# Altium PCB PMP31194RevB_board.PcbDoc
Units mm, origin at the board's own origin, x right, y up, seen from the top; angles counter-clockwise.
Board outline 68.58 x 39.37 mm, 2 copper layers (Top Layer, Bottom Layer), stack 1.575 mm thick; 43 components, 19 nets, 101 pads, 38 vias.
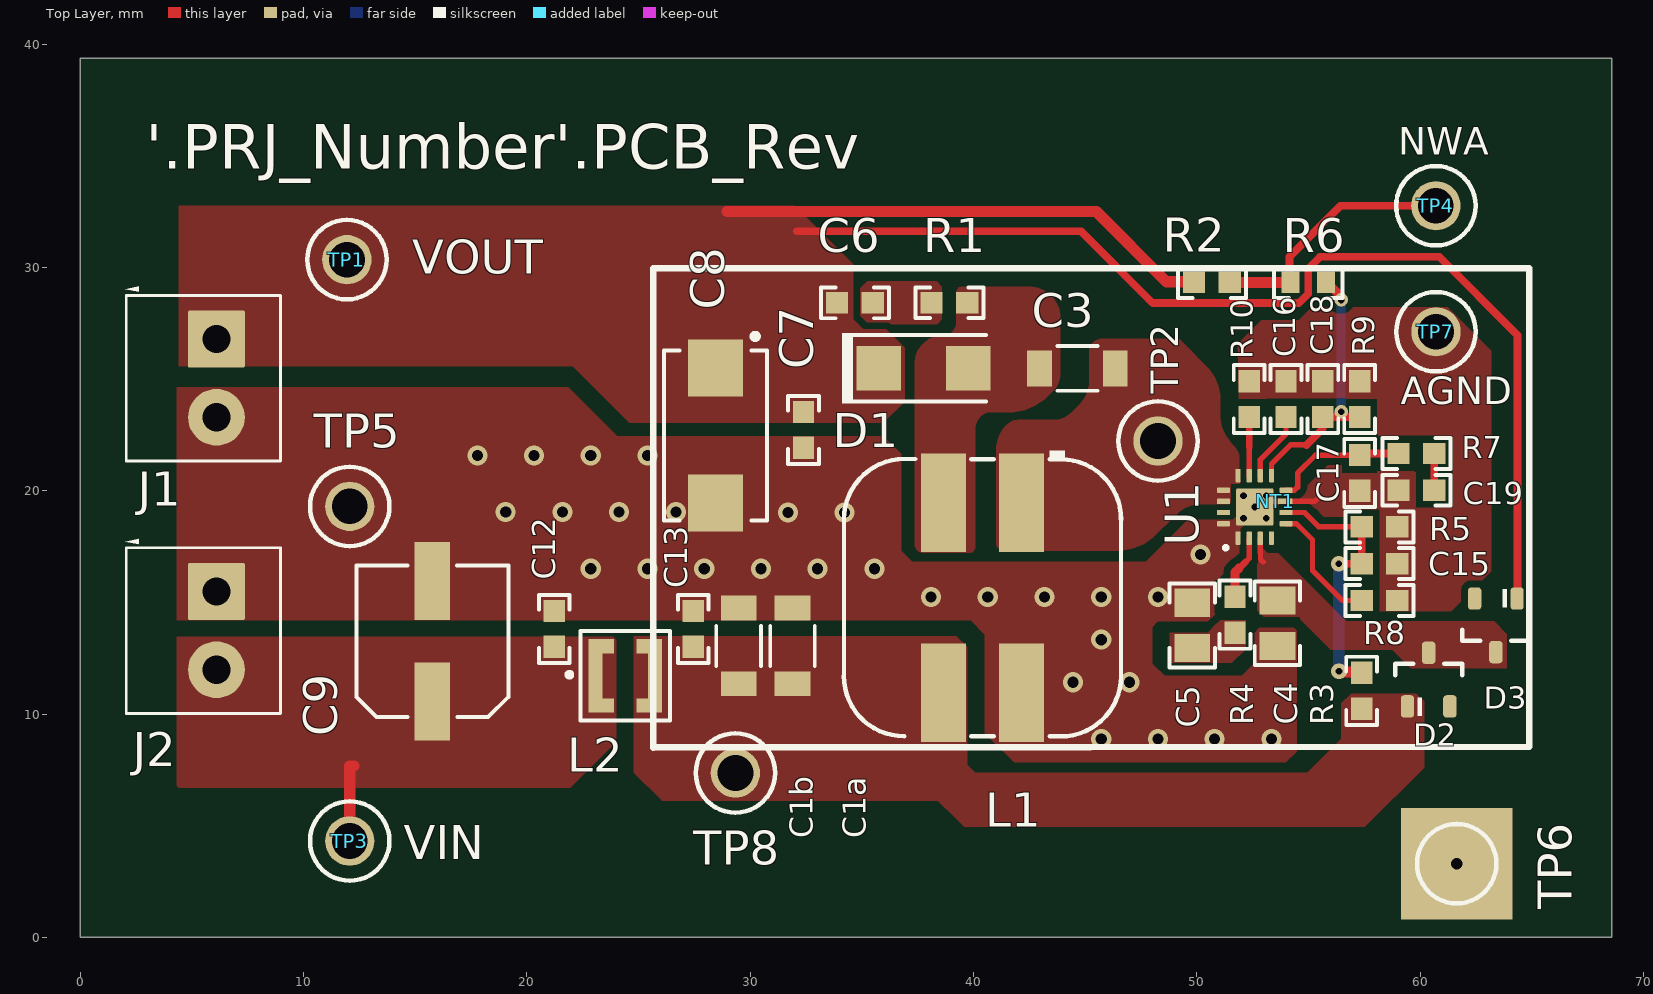
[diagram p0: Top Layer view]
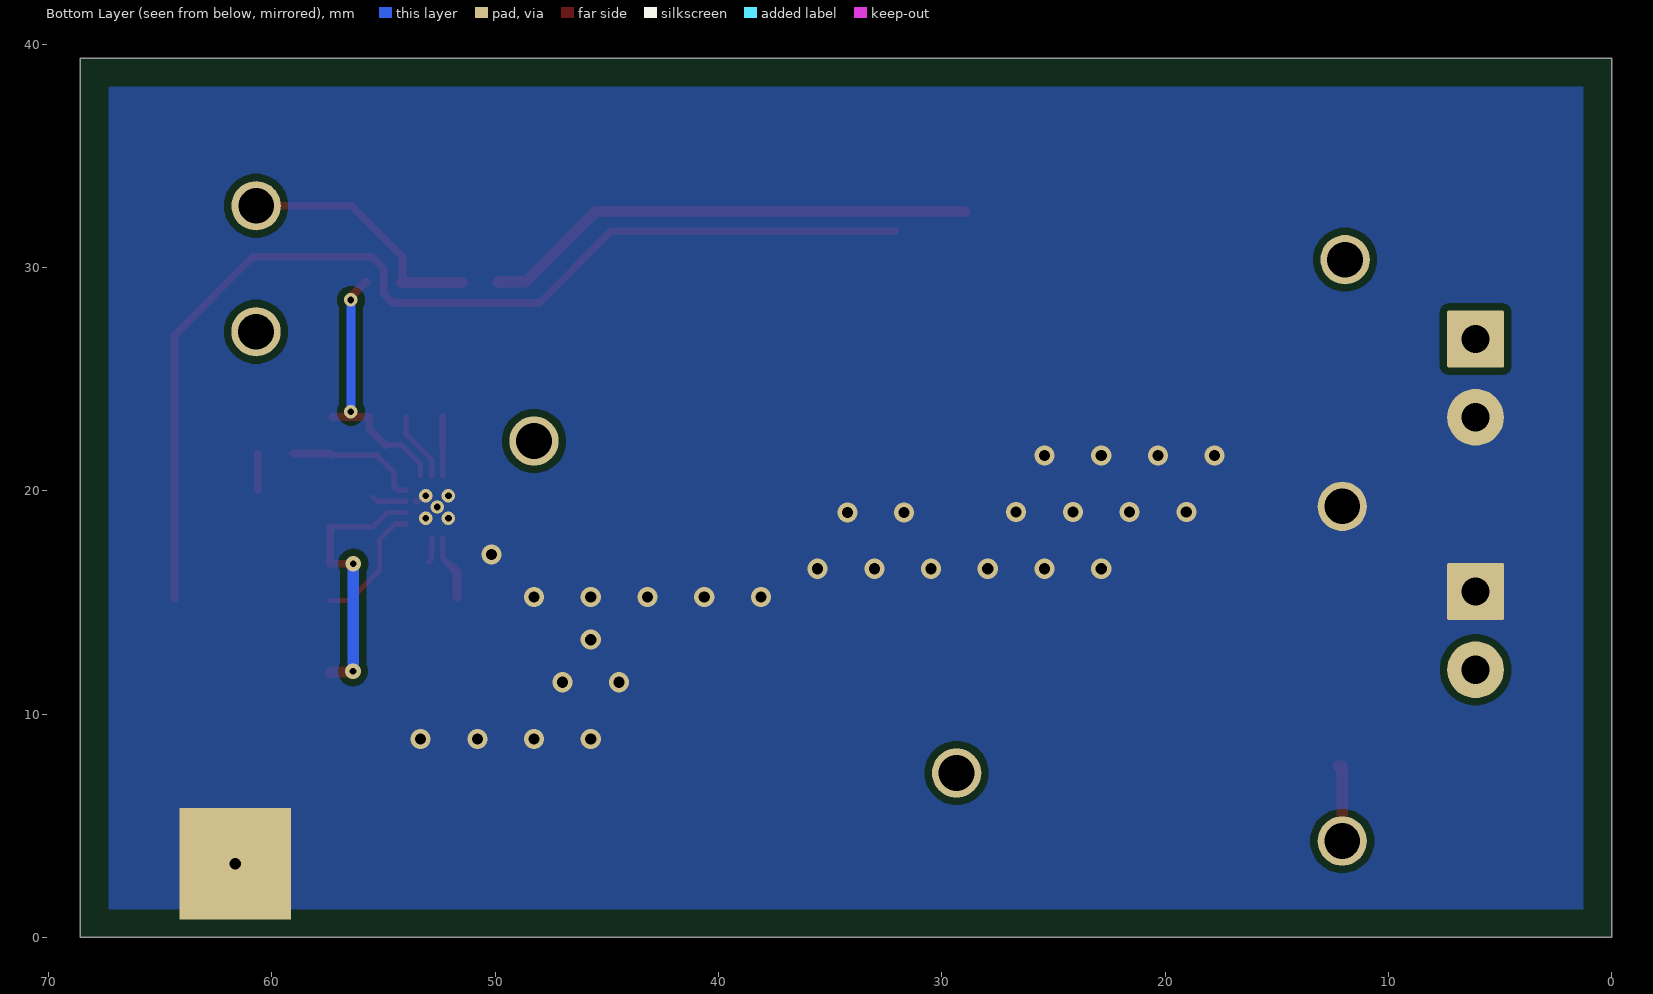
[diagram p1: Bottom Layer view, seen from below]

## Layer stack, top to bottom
Top Solder: solder mask 0.0102, Solder Resist, Dk 3.5
Top Layer: signal copper 0.0356
Dielectric1: core 1.5037, FR-4, Dk 4.8
Bottom Layer: signal copper 0.0356
Bottom Solder: solder mask 0.0102, Solder Resist, Dk 3.5

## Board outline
0,0 68.58,0 68.58,39.37 0,39.37

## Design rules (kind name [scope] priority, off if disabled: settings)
AcuteAngle [All] p1: minimum=4.50000000000000E+0001 checktracksonly=FALSE
AssemblyTestPointUsage [All] p1: valid=2
BoardOutlineClearance BoardOutlineClearance_MountingHoles [OnCopper and InComponentClass('Mounting Holes')] p1: gap=1 ignorepadtopadclearanceinfootprint=FALSE
BoardOutlineClearance BoardOutlineClearance_Poly [OnCopper and IsPoly] p2: gap=0.635 ignorepadtopadclearanceinfootprint=FALSE
BoardOutlineClearance [OnCopper and Not InComponentClass('Logo') and not InComponentClass('FiducialMark') and not InRegion(1000,500,4000,800) and not InPoly] p3: gap=1.905 ignorepadtopadclearanceinfootprint=FALSE
Clearance Clearance_Keepouts [((IsTrack Or IsArc) And Not InPoly) And IsFree and IsKeepOut vs ((IsTrack Or IsArc) And Not InPoly) And IsFree and IsKeepOut] p1: gap=0 ignorepadtopadclearanceinfootprint=FALSE
Clearance Clearance_Poly_U1 [InPolygon vs InComponent('U1')] p2: gap=0.2 ignorepadtopadclearanceinfootprint=TRUE
Clearance Clearance_Poly [InPolygon] p3: gap=0.32 ignorepadtopadclearanceinfootprint=TRUE
Clearance Clearance_FiducialMark [IsKeepOut and InComponentClass('FiducialMark') vs IsPad and InComponentClass('FiducialMark')] p4: gap=0 ignorepadtopadclearanceinfootprint=FALSE
Clearance [All] p5: gap=0.2 ignorepadtopadclearanceinfootprint=TRUE
ComponentClearance ComponentClearance_Net-Tie [HasFootprint('Net-Tie_10mil') vs HasFootprint('RTE0016K')] p1: gap=0 collisioncheckmode=3 verticalgap=0 showdistances=FALSE
ComponentClearance ComponentClearance_MountingHoles_FiducialMarks [InComponentClass('Mounting Holes') vs InComponentClass('FiducialMark')] p2: gap=1.27 collisioncheckmode=3 verticalgap=0.254 showdistances=FALSE
ComponentClearance ComponentClearance_Shunt [InComponentClass('Header') vs InComponentClass('Shunt')] p3: gap=0 collisioncheckmode=3 verticalgap=0 showdistances=FALSE
ComponentClearance ComponentClearance_Logo [InComponentClass('Logo')] p4: gap=1.27 collisioncheckmode=3 verticalgap=0.254 showdistances=FALSE
ComponentClearance ComponentClearance_ScrewToNut [(HasFootprint('NY PMS 440 0025 PH')) vs (HasFootprint('Keystone_1902C'))] p5: gap=0.127 collisioncheckmode=3 verticalgap=0.254 showdistances=FALSE
ComponentClearance ComponentClearance_MountingHoles [InComponentClass('Mounting Holes')] p6: gap=6.35 collisioncheckmode=3 verticalgap=2540 showdistances=FALSE
ComponentClearance ComponentClearance_SmallPassives [HasFootprint('0201*') or HasFootprint('0402*') or HasFootprint('0508') or HasFootprint('0603*') or HasFootprint('0612') or HasFootprint('0805*') or HasFootprint('0815*') or HasFootprint('0830*') or HasFootprint('1206*') or HasFootprint('1210*') or HasFootprint('1808*') or HasFootprint('1812*') or HasFootprint('1825*') or HasFootprint('2010*') or HasFootprint('2220*') or HasFootprint('2225*') or HasFootprint('2512*') or HasFootprint('2728*') or HasFootprint('3518*') vs HasFootprint('0201*') or HasFootprint('0402*') or HasFootprint('0508') or HasFootprint('0603*') or HasFootprint('0612') or HasFootprint('0805*') or HasFootprint('0815*') or HasFootprint('0830*') or HasFootprint('1206*') or HasFootprint('1210*') or HasFootprint('1808*') or HasFootprint('1812*') or HasFootprint('1825*') or HasFootprint('2010*') or HasFootprint('2220*') or HasFootprint('2225*') or HasFootprint('2512*') or HasFootprint('2728*') or HasFootprint('3518*')] p7: gap=0.38 collisioncheckmode=3 verticalgap=0.254 showdistances=FALSE
ComponentClearance ComponentClearance_THtoSMT [IsThruComponent vs IsSMTComponent] p8: gap=1.016 collisioncheckmode=3 verticalgap=0.762 showdistances=FALSE
ComponentClearance ComponentClearance_THtoTH [IsThruComponent vs IsThruComponent] p9: gap=0.762 collisioncheckmode=3 verticalgap=0.762 showdistances=FALSE
ComponentClearance [All] p10: gap=0.762 collisioncheckmode=3 verticalgap=0.254 showdistances=FALSE
DiffPairsRouting [All] p1: maxlimit=2.54 minlimit=0.254 mostfreqgap=0.254 toplayer_minwidth=0.381 toplayer_maxwidth=0.381 toplayer_prefwidth=0.381 bottomlayer_minwidth=0.381 bottomlayer_maxwidth=0.381 bottomlayer_prefwidth=0.381 maxuncoupledlength=25.4
FabricationTestPointUsage TestPointUsage [All] p1: valid=2 allowmultiple=FALSE
FabricationTestpoint Testpoint [All] p1: side=3 testpointundercomponent=TRUE minsize=1.016 maxsize=2.54 preferedsize=1.524 minholesize=0 maxholesize=1.016 preferedholesize=0.813 testpointgrid=0.025 allowsidetop=TRUE allowsidebottom=TRUE usegrid=TRUE gridtolerance=0
FanoutControl Fanout_LCC [IsLCC] p1: bgadir=Out bgaviamode=Centered fanoutstyle=Auto fanoutdirection=Alternating viagrid=0.025 // Fanout_LCC (Default Rule)
FanoutControl Fanout_BGA [IsBGA] p2: bgadir=Out bgaviamode=Centered fanoutstyle=Auto fanoutdirection=Alternating viagrid=0.025 // Fanout_BGA (Default Rule)
FanoutControl Fanout_Default [All] p4: bgadir=Out bgaviamode=Centered fanoutstyle=Auto fanoutdirection=Alternating viagrid=0.025 // Fanout_Default (Default Rule)
FanoutControl Fanout_Small [(CompPinCount < 5)] p5: bgadir=Out bgaviamode=Centered fanoutstyle=Auto fanoutdirection=OutThenIn viagrid=0.025 // Fanout_Small (Default Rule)
HoleSize [All] p1: absolutevalues=TRUE maxlimit=6.375 minlimit=0.3 maxpercent=80.000 minpercent=20.000
MinimumAnnularRing MinimumAnnularRing_ThermalPadVias [IsVia and InAnyComponent] p1: minimumring=0.15
MinimumAnnularRing [All] p2: minimumring=0.2
MinimumSolderMaskSliver MinimumSolderMaskSliver_Logo [InComponentClass('Logo') vs InComponentClass('Logo')] p1: minsoldermaskwidth=0.018
MinimumSolderMaskSliver [All] p2: minsoldermaskwidth=0.1
PlaneConnect [All] p1: planeconnectstyle=Relief reliefexpansion=0.254 reliefentries=4 reliefconductorwidth=0.254 reliefairgap=0.254
PolygonConnect [All] p1: connectstyle=Direct reliefconductorwidth=0.254 reliefentries=4 polygonreliefangle="90 Angle" airgapwidth=0.254
RoutingVias ThermalPadVias [IsVia and InAnyComponent] p1: holewidth=0.2 width=0.5 viastyle="Through Hole" minholewidth=0.2 minwidth=0.5 maxholewidth=0.33 maxwidth=0.6
RoutingVias [All] p2: holewidth=0.5 width=0.9 viastyle="Through Hole" minholewidth=0.3 minwidth=0.6 maxholewidth=1.016 maxwidth=1.651
SilkToBoardRegionClearance [Not ((IsComment or IsDesignator) And (Hide <> 'False')) and not InRegion(1000,500,4000,800)] p1:
SilkToSilkClearance SilkToSilkClearance_Pb-FreeLogo [(HasFootprint('Pb-Free_Overlay_Medium') OR HasFootprint('Pb-Free_Overlay_Small')) vs (HasFootprint('Pb-Free_Overlay_Medium') OR HasFootprint('Pb-Free_Overlay_Small'))] p1: silktosilkclearance=0
SilkToSilkClearance [All] p2: silktosilkclearance=0.1
SilkToSolderMaskClearance SilkToComponentPadClearance [(IsPad or IsFill or IsRegion) and InAnycomponent] p1: minsilkscreentomaskgap=0.127 clearancetoexposedcopper=TRUE
SilkToSolderMaskClearance "Silk to Solder Mask Opening" [All] p2: minsilkscreentomaskgap=0.1 clearancetoexposedcopper=FALSE
SolderMaskExpansion [All] p1: expansion=0.05 istentingtop=FALSE
UnRoutedNet [All] p1: checkbadconnections=TRUE
Width [All] p1: maxlimit=2.54 minlimit=0.152 preferedwidth=0.254 checkconnectedcopper=TRUE
14 further rules are at their usual default settings.

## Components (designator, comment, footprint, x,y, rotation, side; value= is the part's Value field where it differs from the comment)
C1a "GRM31CR71H475KA12L" 1206_180 31.894,13.054 r90 top value=4.7uF
C1b "GRM31CR71H475KA12L" 1206_180 29.481,13.054 r90 top value=4.7uF
C3 "GRM31CR71H475KA12L" 1206_180 44.654,25.483 r0 top value=4.7uF
C4 "GRM21BR71H105KA12L" 0805_HV 53.611,14.07 r90 top value=1uF
C5 "GRM21BR71A105KA01L" 0805_HV 49.801,13.976 r90 top value=1uF
C6 "GCM1885C2A101JA16D" 0603#1 34.688,28.421 r180 top value=100pF
C7 "GRM188R71E104KA01D" 0603#1 32.385,22.733 r270 top value=0.1uF
C8 "T598D227M010ATE025" 7343-31 28.448,22.479 r270 top value=220uF
C9 "EEHZC1H330XP" SM_RADIAL_6.3BMM 15.765,13.266 r90 top value=33uF
C12 "GCM188R71H104KA57D" 0603#1 21.226,13.816 r90 top value=0.1uF
C13 "GCM188R71H104KA57D" 0603#1 27.449,13.816 r90 top value=0.1uF
C15 "GRM1885C1H100JA01D" 0603#1 58.183,16.737 r0 top value=10pF
C16 "GRM188R71E104KA01D" 0603#1 53.992,24.103 r90 top value=0.1uF
C17 "GRM188R71E222KA01D" 0603#1 57.294,20.801 r270 top value=2200pF
C18 "GRM1885C1H470JA01D" 0603#1 55.643,24.103 r90 top value=47pF
C19 "GRM188R71C154KA01D" 0603#1 59.834,20.027 r180 top value=0.15uF
D1 "B360AM-13-F" SMA 37.762,25.483 r0 top value=60V
D2 "ZHCS506TA" SOT-23 60.384,11.547 r90 top value=60V
D3 "ZHCS506TA" SOT-23 63.39,13.976 r270 top value=60V
J1 "ED555/2DS" TERM_BLK_ED555-2DS 6.096,26.797 r270 top
J2 "ED555/2DS" TERM_BLK_ED555-2DS 6.096,15.494 r270 top
L1 "MSC1278-103ML" MSD1278 40.403,15.213 r270 top value=10uH
L2 "LPS3015-102MLB" LPS3015 24.401,11.716 r0 top value=1uH
NT1 "Net-Tie" Net-Tie_10mil 53.517,19.527 r180 top net-tie
R1 "CRCW060310R0JNEAHP" 0603#1 38.917,28.421 r0 top value=10
R2 "CRCW060349R9FKEA" 0603#1 50.673,29.337 r180 top value=49.9
R3 "CRCW0603261KFKEA" 0603#1 57.383,11.047 r270 top value=261k
R4 "CRCW06034R99FKEA" 0603#1 51.706,14.451 r270 top value=4.99
R5 "CRCW060386K6FKEA" 0603#1 58.183,18.388 r180 top value=86.6k
R6 "CRCW060330K1FKEA" 0603#2 54.991,29.337 r180 top value=30.1k
R7 "CPF0603B4K99E" 0603#1 59.834,21.676 r180 top value=4.99k
R8 "CRCW060349K9FKEA" 0603#1 58.183,15.086 r180 top value=49.9k
R9 "CRCW06036K04FKEA" 0603#1 57.294,24.103 r270 top value=6.04k
R10 "CRCW060337K4FKEA" 0603#1 52.345,24.103 r270 top value=37.4k
TP1 "5010" Keystone5010 11.938,30.353 r0 top
TP2 "5012" Keystone5012 48.26,22.231 r0 top
TP3 "5010" Keystone5010 12.065,4.318 r0 top
TP4 "5014" Keystone5014 60.706,32.766 r0 top
TP5 "5011" Keystone5011#1 12.065,19.304 r0 top
TP6 "5011" Keystone5011#2 61.64,3.302 r0 top
TP7 "5011" Keystone5011#1 60.709,27.126 r0 top
TP8 "5010" Keystone5010 29.337,7.366 r0 top
U1 "LM5157QRTERQ1" RTE0016K 52.595,19.277 r90 top

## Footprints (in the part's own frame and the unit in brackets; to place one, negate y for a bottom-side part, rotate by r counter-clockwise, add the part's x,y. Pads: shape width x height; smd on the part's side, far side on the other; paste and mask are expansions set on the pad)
0603#1 [mm] "0603 from SM-752 data"
  rect 1x0.95 smd: 1(-0.8,0) 2(0.8,0)
  silkscreen extent -1.52,-0.69 1.52,0.69, body extent -0.87,-0.47 0.87,0.47, height 1
0603#2 [mm] "0603 from SM-752 data"
  rect 0.8x0.95 smd: 1(-0.8,0) 2(0.8,0)
  silkscreen extent -1.52,-0.69 1.52,0.69, body extent -0.87,-0.47 0.87,0.47, height 1
0805_HV [mil] "0805 with 30mil clearance between pads"
  rect 50x63 smd: 1(-40,0) 2(40,0)
  silkscreen extent -74,-40 74,40, body extent -43,-29 43,29, height 57
1206_180 [mm] "1206_180"
  rect 1.1x1.6 smd: 1(-1.7,0) 2(1.7,0)
  silkscreen extent -0.9,-1 0.9,1, body extent -1.75,-0.95 1.75,0.95, height 1.8
7343-31 [mm] "Medium Density based on Kemet T495 dimensions"
  rect 2.55x2.45 smd: 1(-3.025,0) 2(3.025,0)
  silkscreen extent -4.56,-2.3 3.8,2.3, body extent -3.8,-2.3 3.8,2.3, height 3.1
Keystone5010 [mil] "Keystone Multipurpose loops"
  round 87 hole 63: 1(0,0)
  silkscreen extent -70,-70 70,70, body extent -63,-63 63,62, height 319
Keystone5011#1 [mil] "Keystone Multipurpose loops"
  round 87 hole 63: 1(0,0)
  silkscreen extent -70,-70 70,70, body extent -63,-63 63,62, height 319
Keystone5011#2 [mil] "Keystone Multipurpose loops"
  rect 196.85x196.85 hole 19.68: 1(0,0)
  silkscreen extent -70,-70 70,70, body extent -63,-63 63,62, height 319
Keystone5012 [mil] "Keystone Multipurpose loops"
  round 87 hole 63: 1(0,0)
  silkscreen extent -70,-70 70,70, body extent -63,-63 63,62, height 319
Keystone5014 [mil] "Keystone Multipurpose loops"
  round 87 hole 63: 1(0,0)
  silkscreen extent -70,-70 70,70, body extent -63,-63 63,62, height 319
LPS3015 [mm] "Coilcraft recommended land pattern.  Document 436-2, rev 12/3/08"
  rect 0.63x3.3 smd: 1(-1.335,0) 2(1.335,0)
  rect 1.14x0.64 smd: 1(-1.08,-1.33) 1(-1.08,1.33) 2(1.08,-1.33) 2(1.08,1.33)
  silkscreen extent -2.59,-2 2,2, body extent -1.58,-1.58 1.58,1.58, height 1.52
MSD1278 [mm] "COILCRAFT"
  rect 4.4x2.007 smd mask+0.076: 1(-4.25,1.753) 2(-4.25,-1.753) 3(4.25,-1.753) 4(4.25,1.753)
  silkscreen extent -6.6,-6.21 6.21,6.21, body extent -6.1,-6.1 6.1,6.1, height 7.85
Net-Tie_10mil [mil] "10mil net tie, no solder mask opening, no solder paste"
  rect 10x10 smd paste-5 mask-5: 1(-10,0) 2(10,0)
  Top Layer region: -6,5 6,5 6,-5 -6,-5
RTE0016K [mm] "WQFN-16"
  rrect42% 0.6x0.24 smd paste+0: 1(-1.4,0.75) 2(-1.4,0.25) 3(-1.4,-0.25) 4(-1.4,-0.75) 9(1.4,-0.75) 10(1.4,-0.25) 11(1.4,0.25) 12(1.4,0.75)
  rrect42% 0.24x0.6 smd paste+0: 5(-0.75,-1.4) 6(-0.25,-1.4) 7(0.25,-1.4) 8(0.75,-1.4) 13(0.75,1.4) 14(0.25,1.4) 15(-0.25,1.4) 16(-0.75,1.4)
  rrect6% 1.66x1.66 smd paste-0.075: 17(0,0)
  silkscreen extent -1.86,1.26 -1.79,1.34, body extent -1.5,-1.5 1.5,1.5, height 0.8
SM_RADIAL_6.3BMM [mm] "Nichicon 6.3x7.7"
  rect 3.5x1.6 smd: 1(-2.7,0) 2(2.7,0)
  silkscreen extent -3.4,-3.4 3.4,3.4, body extent -3.4,-3.4 3.4,3.4, height 8
SMA [mm] "Molded Diode, 2-Leads, Body 4.3x2.6mm, IPC Medium Density, based on OnSemi component dimensions and land pattern"
  rect 2x2 smd: 1(-2,0) 2(2,0)
  silkscreen extent -3.66,-1.57 2.79,1.57, body extent -2.6,-1.3 2.6,1.3, height 2.42
SOT-23 [mm] "SOT23, 3-Leads, Body 2.9x1.3mm, Pitch 0.95mm, Lead Span 2.5mm, IPC Medium Density"
  rrect50% 1x0.6 smd: 1(-1.2,0.95) 2(-1.2,-0.95) 3(1.2,0)
  silkscreen extent -1.63,-1.5 0.7,1.5, body extent -1.16,-1.45 1.21,1.45, height 1
TERM_BLK_ED555-2DS [mil]
  rrect4% 100x100 hole 50: 1(0,0)
  round 100 hole 50: 2(138,0)
  silkscreen extent -93,-161 215,113, body extent -69,-150 207,106, height 323

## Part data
C1a C1b C3: "CAP, CERM, 4.7 µF, 50 V,+/- 10%, X7R, 1206", Cap_Case=1206, Manufacturer=MuRata, Supplier Part Number 1=24R6347, TempCo=X7R, Tolerance_%=10, Value2=50V, ValueDisplayed=4.7µF
C4: library part CMP-0008350-2, "CAP, CERM, 1 uF, 50 V, +/- 10%, X7R, 0805", Cap_Case=0805, Manufacturer=MuRata, Supplier Part Number 1=490-4736-1-ND, TempCo=X7R, Tolerance_%=10%, Value1=Unknown, Value2=50V, ValueDisplayed=1uF
C5: library part CMP-0008313-2, "CAP, CERM, 1 uF, 10 V, +/- 10%, X7R, 0805", Cap_Case=0805, Manufacturer=MuRata, Supplier Part Number 1=490-1695-1-ND, TempCo=X7R, Tolerance_%=10%, Value1="0.007 ohm", Value2=10V, ValueDisplayed=1uF
C6: "CAP, CERM, 100 pF, 100 V,+/- 5%, C0G/NP0, AEC-Q200 Grade 1, 0603", Cap_Case=0603, Manufacturer=MuRata, Supplier Part Number 1=490-4771-1-ND, TempCo=C0G/NP0, Tolerance_%=5, Value2=100V, ValueDisplayed=100pF
C7 C16: "CAP, CERM, 0.1 µF, 25 V,+/- 10%, X7R, 0603", Cap_Case=0603, Manufacturer=MuRata, Supplier Part Number 1=490-1524-1-ND, TempCo=X7R, Tolerance_%=10, Value2=25V, ValueDisplayed=0.1µF
C8: "CAP, Tantalum Polymer, 220 µF, 10 V,+/- 20%, 0.025 ohm, AEC-Q200 Grade 1, 7343-31 SMD", Cap_Case=7.3x4.3x3.1mm, Manufacturer=Kemet, Supplier Part Number 1=399-12102-1-ND, Tolerance_%=20, Value1="0.025 ohm", Value2=10V, ValueDisplayed=220µF
C9: "CAP, Polymer Hybrid, 33 µF, 50 V,+/- 20%, 40 ohm, 6.3x7.7 SMD", Manufacturer=Panasonic, Supplier Part Number 1=P15464CT-ND, Tolerance_%=20, Value1="40 ohm", Value2=50V, ValueDisplayed=33µF
C12 C13: "CAP, CERM, 0.1 µF, 50 V,+/- 10%, X7R, 0603", Cap_Case=0603, Manufacturer=MuRata, Supplier Part Number 1=490-4779-1-ND, TempCo=X7R, Tolerance_%=10, Value1="0.02 ohm", Value2=50V, ValueDisplayed=0.1µF
C15: "CAP, CERM, 10 pF, 50 V,+/- 5%, C0G/NP0, 0603", Cap_Case=0603, Manufacturer=MuRata, Supplier Part Number 1=490-1403-1-ND, TempCo=C0G/NP0, Tolerance_%=5, Value2=50V, ValueDisplayed=10pF
C17: "CAP, CERM, 2200 pF, 25 V,+/- 10%, X7R, 0603", Cap_Case=0603, Manufacturer=MuRata, Supplier Part Number 1=GRM188R71E222KA01D-ND, TempCo=X7R, Tolerance_%=10, Value2=25V, ValueDisplayed=2200pF
C18: "CAP, CERM, 47 pF, 50 V,+/- 5%, C0G/NP0, 0603", Cap_Case=0603, Manufacturer=MuRata, Supplier Part Number 1=490-1419-1-ND, TempCo=C0G/NP0, Tolerance_%=5, Value2=50V, ValueDisplayed=47pF
C19: "CAP, CERM, 0.15 µF, 16 V,+/- 10%, X7R, 0603", Cap_Case=0603, Manufacturer=MuRata, Supplier Part Number 1=490-3292-1-ND, TempCo=X7R, Tolerance_%=10, Value2=16V, ValueDisplayed=0.15µF
D1: "Diode, Schottky, 60 V, 3 A, AEC-Q101, SMA", Manufacturer="Diodes Inc.", Supplier Part Number 1=B360AM-13-FDICT-ND, Value1=3A, Value2=0.7V
D2 D3: "Diode, Schottky, 60 V, 0.5 A, SOT-23", Manufacturer="Diodes Inc.", Supplier Part Number 1=ZHCS506CT-ND, Value1=0.5A, Value2=0.63V
J1 J2: library part CMP-0074913-1, "Terminal Block, 3.5mm Pitch, 2x1, TH", Color=Grey, Current_A=6A, Manufacturer="On-Shore Technology", Supplier Part Number 1=ED1514-ND, Voltage_V=150V
L1: library part MSD1278-103ML, "Coupled inductor, 10 µH, 10.5 A, 0.058 ohm, AEC-Q200 Grade 3, TH", Manufacturer=Coilcraft, ValueDisplayed=10µH
L2: "Inductor, Shielded Drum Core, Ferrite, 1 µH, 2 A, 0.08 ohm, SMD", Manufacturer=Coilcraft, Value1="0.08 ohm", Value2=2A, ValueDisplayed=1µH
NT1: "Single point connection between nets."
R1: "RES, 10, 5%, 0.25 W, 0603", Manufacturer=Vishay-Dale, Power_W=0.25, Supplier Part Number 1=541-10SACT-ND, TempCo="200 ppm/C", Tolerance_%=5, Value1=5%, Value2=0.25W, Value_Code=10R0, ValueDisplayed=10
R2: library part CMP-0022448-4, "RES, 49.9, 1%, 0.1 W, AEC-Q200 Grade 0, 0603", Manufacturer=Vishay-Dale, Power_W=100mW, Supplier Part Number 1=541-49.9HCT-ND, TempCo="100 ppm/C", Tolerance_%=1%, Value2=0.1W, Value_Code=49R9, ValueDisplayed=49.9
R3: "RES, 261 k, 1%, 0.1 W, 0603", Manufacturer=Vishay-Dale, Power_W=0.1, Supplier Part Number 1=541-261KHCT-ND, TempCo="100 ppm/C", Tolerance_%=1, Value1=1%, Value2=0.1W, Value_Code=261k
R4: "RES, 4.99, 1%, 0.1 W, 0603", Manufacturer=Vishay-Dale, Power_W=0.1, Supplier Part Number 1=541-4.99HHCT-ND, TempCo="100 ppm/C", Tolerance_%=1, Value1=1%, Value2=0.1W, Value_Code=4R99, ValueDisplayed=4.99
R5: "RES, 86.6 k, 1%, 0.1 W, 0603", Manufacturer=Vishay-Dale, Power_W=0.1, Supplier Part Number 1=541-86.6KHCT-ND, TempCo="100 ppm/C", Tolerance_%=1, Value1=1%, Value2=0.1W, Value_Code=86k6, ValueDisplayed=86.6k
R6: "RES, 30.1 k, 1%, 0.1 W, 0603", Manufacturer=Vishay-Dale, Power_W=0.1, Supplier Part Number 1=541-30.1KHCT-ND, TempCo="100 ppm/C", Tolerance_%=1, Value1=1%, Value2=0.1W, Value_Code=30k1, ValueDisplayed=30.1k
R7: "RES, 4.99 k, 0.1%, 0.063 W, 0603", Manufacturer="TE Connectivity", Power_W=0.063, Supplier Part Number 1=8-1879219-3-ND, TempCo="25 ppm/C", Tolerance_%=0.1, Value1=0.1%, Value2=0.063W, Value_Code=4k99, ValueDisplayed=4.99k
R8: "RES, 49.9 k, 1%, 0.1 W, 0603", Manufacturer=Vishay-Dale, Power_W=0.1, Supplier Part Number 1=541-49.9KHCT-ND, TempCo="100 ppm/C", Tolerance_%=1, Value1=1%, Value2=0.1W, Value_Code=49k9, ValueDisplayed=49.9k
R9: "RES, 6.04 k, 1%, 0.1 W, 0603", Manufacturer=Vishay-Dale, Power_W=0.1, Supplier Part Number 1=541-6.04KHCT-ND, TempCo="100 ppm/C", Tolerance_%=1, Value1=1%, Value2=0.1W, Value_Code=6k04, ValueDisplayed=6.04k
R10: library part CMP-0022360-4, "RES, 37.4 k, 1%, 0.1 W, AEC-Q200 Grade 0, 0603", Manufacturer=Vishay-Dale, Power_W=100mW, Supplier Part Number 1=541-37.4KHCT-ND, TempCo="100 ppm/C", Tolerance_%=1%, Value2=0.1W, Value_Code=37k4, ValueDisplayed=37.4k
TP1 TP3 TP8: library part CMP-0055147-1, "Test Point, Multipurpose, Red, TH", Color=Red, Manufacturer=Keystone, Supplier Part Number 1=36-5010-ND
TP2: "Test Point, Multipurpose, White, TH", Color=White, Manufacturer=Keystone, Supplier Part Number 1=36-5012-ND
TP4: library part CMP-0055151-1, "Test Point, Multipurpose, Yellow, TH", Color=Yellow, Manufacturer=Keystone, Supplier Part Number 1=36-5014-ND
TP5 TP6 TP7: library part CMP-0055148-1, "Test Point, Multipurpose, Black, TH", Color=Black, Manufacturer=Keystone, Supplier Part Number 1=36-5011-ND
U1: library part CMP-0861102-1, "2.2MHz Wide VIN Boost/Sepic/Flyback Converter with Dual Random Spread Spectrum, RTE0016K (WQFN-16)", Alternate Manufacturer="Texas Instruments"

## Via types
v1: diameter 0.9, hole 0.5, Top Layer to Bottom Layer, tented top, 23 vias
v2: diameter 0.9, hole 0.5, Top Layer to Bottom Layer, 6 vias
v3: diameter 0.6, hole 0.3, Top Layer to Bottom Layer, 5 vias
v4: diameter 0.6, hole 0.3, Top Layer to Bottom Layer, tented both sides, 2 vias
v5: diameter 0.7, hole 0.3, Top Layer to Bottom Layer, tented both sides, 2 vias

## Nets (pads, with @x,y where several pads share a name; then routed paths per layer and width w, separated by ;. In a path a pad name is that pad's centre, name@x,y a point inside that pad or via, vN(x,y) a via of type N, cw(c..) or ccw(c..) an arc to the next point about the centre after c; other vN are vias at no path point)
AGND: C15.2 C16.2 C17.2 C18.2 C19.2 NT1.1 R5.1 R8.1 R9.1 R10.1 TP7.1 U1.7 | length 1.5
  Top Layer w0.24: U1.7 55.283,19.527 55.466,19.71
GND: C1a.2 C1b.2 C4.1 C5.2 C7.2 C8.2 C9.2 C12.2 C13.2 J1.2 J2.1 L1.4 NT1.2 TP5.1 TP6.1 U1.1 U1.16 U1.17
  other v1: 45.72,8.89 48.26,8.89 50.8,8.89 53.34,8.89 44.45,11.43 46.99,11.43 45.72,13.335 38.1,15.24 40.64,15.24 43.18,15.24 45.72,15.24 48.26,15.24 22.86,16.51 25.4,16.51 27.94,16.51 30.48,16.51 33.02,16.51 35.56,16.51 50.165,17.145 34.218,19.027 24.13,19.05 26.67,19.05 25.4,21.59
  other v2: 31.694,19.027 19.05,19.05 21.59,19.05 17.78,21.59 20.32,21.59 22.86,21.59
  other v3: 52.095,18.771 53.111,18.771 52.595,19.277 52.095,19.787 53.111,19.787
NetC3_1: C3.1 D1.2 L1.2 R1.2
NetC3_2: C3.2 L1.1 TP2.1 U1.12 U1.13 U1.14
NetC4_2: C4.2 D2.3 D3.3 U1.3 | length 1.1
  Top Layer w0.24: U1.3 52.845,17.22 52.853,17.212 52.853,16.932 52.972,16.813
NetC5_1: C5.1 R4.2
NetC6_1: C6.1 R1.1
NetC9_1: C9.1 C12.1 J2.2 L2.1 TP3.1 | length 3.5
  Top Layer w0.5: TP3.1 12.065,7.671 12.253,7.671
NetC15_1: C15.1 R3.1 R5.2 U1.6 | length 12.2
  Top Layer w0.24: U1.6 54.83,19.027 55.469,18.388 R5.2
  Top Layer w0.35: v5(56.351,16.737) C15.1 R5.2
  Top Layer w0.5: v5(56.368,11.922) 56.406,11.884 57.346,11.884 R3.1
  Bottom Layer w0.5: v5(56.351,16.737) 56.36,16.729 56.36,11.931 v5(56.368,11.922)
NetC16_1: C16.1 U1.10 | length 3.1
  Top Layer w0.24: U1.10 52.845,21.406 53.992,22.553 C16.1
NetC17_1: C17.1 R7.2 U1.8 | length 6.1
  Top Layer w0.24: U1.8 54.375,20.027 54.516,20.168 54.516,20.801 55.305,21.59 57.283,21.59 C17.1
  Top Layer w0.35: C17.1 57.369,21.676 R7.2
NetC19_1: C19.1 R7.1 | length 1.6
  Top Layer w0.35: C19.1 R7.1
NetR2_1: R2.1 R6.2 TP4.1 | length 11.4
  Top Layer w0.35: R6.2 54.153,29.375 54.153,30.48 56.439,32.766 TP4.1
  Top Layer w0.5: R2.1 R6.2
NetR4_1: R4.1 U1.2 | length 2.9
  Top Layer w0.24: 52.181,16.813 52.345,16.977 U1.2
  Top Layer w0.3: 51.898,16.543 51.911,16.543 52.181,16.813
  Top Layer w0.4: R4.1 51.706,16.351 51.898,16.543
NetR8_2: R8.2 U1.5 | length 5.6
  Top Layer w0.24: U1.5 54.467,18.527 55.184,17.811 55.184,16.428 56.526,15.086 R8.2
NetR10_2: R10.2 U1.11 | length 2.6
  Top Layer w0.24: U1.11 52.345,21.952
  Top Layer w0.3: 52.345,21.952 R10.2
VFB: C18.1 R6.1 R9.2 U1.9 | length 12
  Top Layer w0.24: U1.9 53.345,21.201 54.201,22.057 54.918,22.057
  Top Layer w0.35: 54.918,22.057 55.643,22.782 C18.1 v4@56.368,23.303 ; v4(56.464,23.546) 56.416,23.498 56.416,23.351 v4@56.368,23.303 ; R9.2 v4@56.368,23.303
  Top Layer w0.4: R6.1 55.816,29.337 56.426,28.727 56.426,28.588 v4(56.464,28.55)
  Bottom Layer w0.4: v4(56.464,23.546) v4(56.464,28.55)
VIN: C1a.1 C1b.1 C13.1 D2.1 L1.3 L2.2 R3.2 TP8.1
VOUT: C6.2 C7.1 C8.1 D1.1 D3.1 J1.1 R2.2 TP1.1 | length 71.1
  Top Layer w0.35: TP1.1@11.582,30.709 TP1.1 ; 32.099,31.626 44.816,31.626 48.034,28.407 54.567,28.407 54.991,28.832 54.991,29.949 55.522,30.48 60.852,30.48 64.364,26.968 64.364,15.2 D3.1
  Top Layer w0.5: 28.956,32.512 45.497,32.512 48.646,29.362 49.848,29.362 R2.2
pads on no net: D2.2 D3.2 U1.4 U1.15

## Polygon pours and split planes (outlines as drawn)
NetC6_1 on Top Layer "TOP_LAYER_NETC6_1_P010" (solid, remove dead copper, pour order 10): 34.925,27.686 34.925,29.062 35.238,29.375 38.36,29.375 38.588,29.146 38.588,27.686 38.367,27.465 35.146,27.465
AGND on Top Layer "TOP_LAYER_AGND_P009" (solid, remove dead copper, pour order 9): 55.866,21.141 54.582,19.857 53.814,19.857 53.67,19.713 53.67,19.4 53.858,19.213 55.317,19.213 55.866,18.664 55.866,16.054 57.308,14.611 61.393,14.611 63.191,16.409 63.191,26.266 61.231,28.226 55.153,28.226 54.567,27.64 52.889,27.64 51.843,26.593 51.87,24.103 53.914,24.103 55.866,22.151
NetC3_1 on Top Layer "TOP_LAYER_NETC3_1_P008" (solid, remove dead copper, pour order 8): 40.082,22.791 cw(c40.812,22.791) 40.812,23.521 41.547,23.521 ccw(c41.547,26.061) 43.343,24.265 43.612,24.533 ccw(c42.947,25.198) 43.887,25.198 43.887,27.742 ccw(c42.483,27.742) 42.483,29.146 39.487,29.146 ccw(c39.487,28.896) 39.237,28.896 39.237,27.556 cw(c38.651,27.556) 38.651,26.969 ccw(c38.651,25.686) 37.367,25.686 37.367,17.615 ccw(c37.762,17.615) 37.762,17.22 39.83,17.22 ccw(c39.83,17.472) 40.082,17.472
NetC3_2 on Top Layer "TOP_LAYER_NETC3_2_P007" (solid, remove dead copper, pour order 7): 50.201,19.4 ccw(c50.201,17.81) 49.076,18.934 48.211,18.069 cw(c46.415,19.865) 46.415,17.325 41.359,17.325 cw(c41.359,17.663) 41.021,17.663 41.021,21.838 cw(c42.597,21.838) 41.483,22.952 cw(c42.036,22.4) 42.036,23.181 43.612,23.181 ccw(c43.612,24.264) 44.377,23.498 44.755,23.876 ccw(c43.712,24.918) 45.187,24.918 45.187,26.238 cw(c45.766,26.238) 45.766,26.818 49.076,26.818 cw(c49.076,26.544) 49.27,26.738 50.432,25.575 cw(c48.96,24.103) 51.042,24.103 51.042,23.453 ccw(c53.016,23.453) 51.62,22.057 cw(c50.79,21.226) 51.965,21.226 51.965,20.394 cw(c51.897,20.394) 51.897,20.326 51.598,20.326 ccw(c51.598,20.251) 51.523,20.251 51.523,19.498 cw(c51.426,19.498) 51.426,19.4
NetC5_1 on Top Layer "TOP_LAYER_NETC5_1_P006" (solid, remove dead copper, pour order 6): 48.785,12.296 51.576,12.296 52.181,12.901 52.181,14.201 51.042,14.201 50.492,13.651 48.785,13.651
VIN on Top Layer "TOP_LAYER_VIN_P002" (solid, remove dead copper, pour order 2): 39.134,8.756 39.134,8.313 40.082,7.366 54.942,7.366 56.466,8.89 56.466,10.479 56.908,10.922 59.834,10.922 60.184,10.572 60.184,7.606 57.531,4.953 39.577,4.953 38.042,6.488 38.042,8.756
NetC4_2 on Top Layer "TOP_LAYER_NETC4_2_P003" (solid, remove dead copper, pour order 3): 63.89,12.051 59.582,12.051 58.757,12.876 56.007,12.876 54.627,14.256 54.627,14.361 53.001,14.361 52.705,14.658 52.705,18.161 52.959,18.161 52.959,17.429 53.175,17.212 53.654,17.212 56.715,14.151 63.315,14.151 63.89,13.576
GND on Top Layer "TOP_LAYER_GND_P004" (solid, remove dead copper, pour order 4): 40.513,13.562 40.513,9.144 41.817,7.84 53.994,7.84 54.467,8.313 54.467,13.733 54.336,13.864 52.808,13.864 52.595,13.651 52.595,12.296 52.015,11.716 48.556,11.716 48.006,12.266 48.006,13.897 48.26,14.151 50.492,14.151 50.817,14.476 50.784,14.509 50.784,16.012 50.895,16.012 51.956,17.073 51.956,18.302 52.345,18.691 52.345,18.934 51.845,18.934 51.608,18.697 49.588,18.697 47.704,16.813 37.262,16.813 36.757,17.318 36.757,21.663 35.968,22.452 24.043,22.452 21.859,24.636 4.318,24.636 4.318,14.201 14.859,14.201 39.874,14.201
VOUT on Top Layer "TOP_LAYER_VOUT_P005" (solid, remove dead copper, pour order 5): 4.401,25.578 22.043,25.578 24.576,23.044 35.963,23.044 36.916,23.997 36.916,26.402 36.085,27.233 35.075,27.233 34.612,27.696 34.612,30.158 32.004,32.766 4.401,32.766
VIN on Top Layer "TOP_LAYER_VIN_P001" (solid, remove dead copper, pour order 1): 24.79,13.482 24.79,7.383 26.052,6.121 39.134,6.121 39.717,6.704 39.717,13.016 39.237,13.497
NetC9_1 on Top Layer "TOP_LAYER_NETC9_1_P000" (solid, remove dead copper, pour order 0): 4.327,13.462 14.605,13.462 23.876,13.462 24.003,13.335 24.003,8.756 21.951,6.704 4.311,6.704
GND on Bottom Layer "BOTTOM_LAYER_GND_P011" (solid, remove dead copper, pour order 11): 67.31,38.1 1.27,38.1 1.27,1.27 67.31,1.27

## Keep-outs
Keep-Out Layer:
  text ".Layer_Name" at 14.656,-21.806 h1.52

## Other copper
Top Layer:
  text ".Layer_Name" at 14.656,-21.806 h1.52
Bottom Layer:
  text ".Layer_Name" at 14.656,-21.806 h1.52

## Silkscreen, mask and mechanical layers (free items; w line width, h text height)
Top Overlay:
  lines w0.3: 25.654,8.509 64.89,8.535 64.89,29.972 25.908,29.972 25.654,29.972 25.654,8.535
  text "NWA" at 59.011,35.052 h1.22
  text "'.PRJ_Number'.PCB_Rev" at 2.921,34.417 h2
  text "VOUT" at 14.859,29.732 h1.52
  text "AGND" at 59.138,23.882 h1.22
  text "VIN" at 14.478,3.505 h1.52
  text ".Layer_Name" at 14.656,-21.806 h1.52
Bottom Overlay:
  text ".Layer_Name" at 14.656,-21.806 h1.52
Top Paste:
  text ".Layer_Name" at 14.656,-21.806 h1.52
Bottom Paste:
  text ".Layer_Name" at 14.656,-21.806 h1.52
Top Solder:
  text ".Layer_Name" at 14.656,-21.806 h1.52
  text ".Layer_Name" at 14.656,-21.806 h1.52
Bottom Solder:
  text "'.PRJ_Number''.PCB_Rev'" at 51.448,34.844 h2
  text ".Layer_Name" at 14.656,-21.806 h1.52
Drill Guide:
  text ".Layer_Name" at 14.656,-21.806 h1.52
M1 Board Outline:
  the board outline again, w0.254
  text ".Layer_Name" at 14.656,-21.806 h1.52
M2 Board Dimensions:
  rectangle: 0,-6.985 3.175,-3.81
  rectangle: 3.175,-10.16 12.7,-6.985
  lines w0.178: 0,-6.985 25.4,-6.985 ; 3.175,-10.16 3.175,-3.81 ; 6.35,-10.16 6.35,-3.81 ; 12.7,-10.16 12.7,-3.81 ; 19.05,-10.16 19.05,-3.81 ; 0,-10.16 25.4,-10.16 25.4,-3.81 0,-3.81 0,-10.16
  text "'.Print_Date' '.Print_Time'" at 2.769,40.621 h2
  text ".Layer_Name" at 14.656,-21.806 h1.52
M3 3D STEP Top:
  text ".Layer_Name" at 14.656,-21.806 h1.52
M4 3D STEP Bottom:
  text ".Layer_Name" at 14.656,-21.806 h1.52
M5 Assembly Top:
  lines w0.254: -7.417,-23.626 160.223,-23.626 ; -7.417,-18.462 160.274,-18.462 ; -7.417,-13.297 -7.417,-28.791 94.31,-28.791 160.274,-28.791 160.274,-13.297 -7.404,-13.297 -7.404,-28.791 32.614,-28.791 ; 55.194,-28.791 55.194,-13.297 ; 87.376,-18.462 87.376,-13.297 ; 108.712,-18.462 108.712,-13.297 ; 124.511,-28.956 124.511,-23.804
  text "COMPONENTS MARKED 'DNP' SHOULD NOT BE POPULATED." at 29.299,-8.09 h1.52
  text "ASSEMBLY VARIANT:" at 29.286,-11.024 h1.52
  text ".VariantName" at 55.601,-11.024 h1.52
  text "PCB VIEWED FROM TOP SIDE" at -5.804,-16.654 h1.52
  text "BOARD #:" at 57.099,-16.654 h1.52
  text ".PRJ_Number" at 70.955,-16.654 h1.52
  text "REV:" at 92.405,-16.654 h1.52
  text ".PCB_Rev" at 99.809,-16.654 h1.52
  text "SVN REV:" at 113.69,-16.654 h1.52
  text ".VersionControl_RevNumber" at 126.543,-16.654 h1.52
  text "TID #:" at 57.099,-21.819 h1.52
  text ".TID" at 70.955,-21.819 h1.52
  text "PLOT NAME =" at -5.804,-27.034 h1.52
  text ".plot_File_Name" at 14.656,-27.034 h1.52
  text "GENERATED    :" at 57.15,-27.034 h1.52
  text ".Print_Date" at 79.235,-27.034 h1.52
  text ".Print_Time" at 97.752,-27.034 h1.52
  text "TEXAS INSTRUMENTS" at 129.87,-27.034 h1.52
M6 Assembly Bottom:
  lines w0.254: -7.429,-18.474 160.261,-18.474 ; -7.379,-23.639 160.261,-23.639 ; 28.334,-28.969 28.334,-23.817 ; 44.133,-18.474 44.133,-13.31 ; 65.468,-18.474 65.468,-13.31 ; 97.65,-28.804 97.65,-13.31 ; 120.231,-28.804 160.249,-28.804 160.249,-13.31 -7.429,-13.31 -7.429,-28.804 58.534,-28.804 160.261,-28.804 160.261,-13.31
  text "COMPONENTS MARKED 'DNP' SHOULD NOT BE POPULATED." at 154.991,-8.077 h1.52
  text ".VariantName" at 128.473,-11.024 h1.52
  text "ASSEMBLY VARIANT:" at 154.864,-11.024 h1.52
  text ".VersionControl_RevNumber" at 26.302,-16.667 h1.52
  text "SVN REV:" at 39.154,-16.667 h1.52
  text ".PCB_Rev" at 53.035,-16.667 h1.52
  text "REV:" at 60.439,-16.667 h1.52
  text ".PRJ_Number" at 81.89,-16.667 h1.52
  text "BOARD #:" at 95.745,-16.667 h1.52
  text "PCB VIEWED FROM BOTTOM SIDE" at 158.648,-16.667 h1.52
  text ".TID" at 81.89,-21.831 h1.52
  text "TID #:" at 95.745,-21.831 h1.52
  text "TEXAS INSTRUMENTS" at 22.974,-27.047 h1.52
  text ".Print_Time" at 55.093,-27.047 h1.52
  text ".Print_Date" at 73.609,-27.047 h1.52
  text "GENERATED    :" at 95.694,-27.047 h1.52
  text ".plot_File_Name" at 138.189,-27.047 h1.52
  text "PLOT NAME =" at 158.648,-27.047 h1.52
M9 Title Sheet:
  drawing of 57 lines, arcs and shapes, not listed
  text "1" at 18.792,204.127 h1.78
  text "2" at 82.182,204.127 h1.78
  text "3" at 145.411,204.127 h1.78
  text "4" at 209.08,204.127 h1.78
  text "5" at 272.555,204.127 h1.78
  text "6" at 336.182,204.127 h1.78
  text "A" at -10.579,175.095 h1.78
  text "A" at 365.341,175.095 h1.78
  text "B" at -10.579,114.643 h1.78
  text "B" at 365.341,114.643 h1.78
  text "C" at -10.579,54.318 h1.78
  text "C" at 365.341,54.318 h1.78
  text "PROJECT TITLE:" at 288.125,7.048 h1.14
  text ".PRJ_Title" at 289.395,3.662 h1.78
  text "DESIGNED FOR:" at 288.125,-0.597 h1.14
  text ".PRJ_Customer" at 289.395,-4.153 h1.78
  text "D" at -10.579,-5.88 h1.78
  text "D" at 365.341,-5.88 h1.78
  text "FILE NAME:" at 288.125,-8.217 h1.14
  text ".PCB_File_Name_No_Path" at 289.395,-11.265 h1.78
  text "Texas Instruments (TI) and/or its licensors do not warrant the accuracy or completeness of this specification" at 161.9,-15.376 h1.14
  text "ENGINEER:" at 288.125,-15.583 h1.14
  text "LAYOUT BY:" at 326.352,-15.583 h1.14
  text "or any information contained therein. TI and/or its licensors do not warrant that this design will meet" at 160.757,-18.237 h1.14
  text ".PRJ_Engineer" at 289.395,-19.52 h1.78
  text ".PCB_Layout" at 327.635,-19.52 h1.78
  text "the specifications, will be suitable for your application or fit for any particular purpose, or will operate in" at 160.757,-21.099 h1.14
  text ".Layer_Name" at 14.656,-21.806 h1.52
  text "ALTIUM DESIGNER VERSION:" at 326.352,-23.457 h1.14
  text "an implementation. TI and/or its licensors do not warrant that the design is production worthy. You should" at 160.757,-23.961 h1.14
  text "completely validate and test your design implementation to confirm the system functionality for your application." at 161.9,-26.822 h1.14
  text ".print_Scale" at 289.395,-26.843 h1.78
  text ".Application_BuildNumber" at 327.635,-26.843 h1.78
  text "1" at 18.792,-32.093 h1.78
  text "2" at 82.182,-32.093 h1.78
  text "3" at 145.411,-32.093 h1.78
  text "4" at 209.08,-32.093 h1.78
  text "5" at 272.555,-32.093 h1.78
  text "6" at 336.182,-32.093 h1.78
M10 Fab Notes:
  drawing of 189 lines, arcs and shapes, not listed
  text "DESIGN INFORMATION" at 314.503,161.447 h1.52
  text "MIN. TRACK WIDTH:" at 298.131,158.091 h1.52
  text "8" at 325.976,158.091 h1.52
  text "MIL" at 329.907,158.091 h1.52
  text "MIN. CLEARANCE:" at 298.131,154.938 h1.52
  text "0.2" at 324.452,154.938 h1.52
  text "mm" at 329.907,154.938 h1.52
  text "MIN. VIA PAD SIZE:" at 298.131,151.785 h1.52
  text "24" at 325.214,151.785 h1.52
  text "MIL" at 329.907,151.785 h1.52
  text "0.05mm (2MIL)" at 315.784,148.486 h1.52
  text "MINIMUM ANNULAR RING" at 289.769,148.277 h1.52
  text "EXTERNAL" at 333.768,148.277 h1.52
  text "PER" at 294.849,145.48 h1.52
  text "IPC-D-275 CLASS 2 LEVEL C" at 300.437,145.48 h1.52
  text "MIL, HOLES" at 338.238,142.928 h1.52
  text "+/-" at 328.27,142.709 h1.52
  text "+/-" at 349.961,142.709 h1.52
  text "REGISTRATION TOLERANCES:" at 289.769,142.682 h1.52
  text "METAL" at 320.243,142.682 h1.52
  text "5" at 334.879,142.683 h1.52
  text "3" at 356.037,142.683 h1.52
  text "MIL" at 358.99,142.682 h1.52
  text "HOLE SIZE TOLERANCE (UNLESS OTHERWISE SPECIFIED):" at 289.769,140.185 h1.52
  text "+/-" at 349.961,140.112 h1.52
  text "3" at 356.037,140.085 h1.52
  text "MIL" at 358.99,140.085 h1.52
  text "MATERIAL:" at 287.87,136.589 h1.52
  text "FR-4 High Tg" at 312.926,133.324 h1.52
  text "X" at 309.257,133.122 h1.52
  text "FR-408" at 298.563,133.007 h1.52
  text "OTHER" at 336.358,133.007 h1.52
  text "62 MIL (1.6mm) +/-10%" at 306.694,129.374 h1.52
  text "X" at 303.643,129.312 h1.52
  text "THICKNESS:" at 289.769,129.165 h1.52
  text "OTHER" at 339.33,129.165 h1.52
  text "TOLERANCE:" at 289.769,125.652 h1.52
  text "X" at 311.314,125.652 h1.52
  text "ANSI IPC-6012 TYPE 3 CLASS 2" at 315.836,125.652 h1.52
  text "OTHER +/-" at 315.835,121.989 h1.52
  text "BOW & TWIST:" at 289.769,118.302 h1.52
  text "X" at 311.314,118.302 h1.52
  text "ANSI IPC-6012 TYPE 3 CLASS 2" at 315.836,118.302 h1.52
  text "OTHER +/-" at 315.835,114.576 h1.52
  text "DRILLING:" at 287.87,111.258 h1.52
  text "NC_DRILL FILES" at 332.599,108.586 h1.52
  text "REFERENCE:" at 289.769,108.486 h1.52
  text "X" at 306.463,108.484 h1.52
  text "AS SHOWN" at 310.984,108.486 h1.52
  text "X" at 329.348,108.486 h1.52
  text "OTHER" at 340.168,104.873 h1.52
  text "PTH COPPER THICKNESS:" at 289.761,104.783 h1.52
  text "X" at 318.697,104.783 h1.52
  text "20-30 um" at 321.948,104.783 h1.52
  text "BOARD FINISH:" at 287.87,101.034 h1.52
  text "SILKSCREEN:" at 291.812,98.237 h1.52
  text "X" at 316.14,98.237 h1.52
  text "TOP" at 319.112,98.237 h1.52
  text "X" at 329.094,98.237 h1.52
  text "BOTTOM" at 332.091,98.237 h1.52
  text "SILKSCREEN COLOR:" at 291.812,94.295 h1.52
  text "X" at 316.115,94.295 h1.52
  text "WHITE" at 319.112,94.295 h1.52
  text "OTHER" at 332.091,94.295 h1.52
  text "X" at 319.442,90.652 h1.52
  text "GREEN" at 322.439,90.652 h1.52
  text "OTHER" at 338.136,90.652 h1.52
  text "SOLDER RESIST COLOR:" at 291.812,90.477 h1.52
  text "X" at 319.442,86.734 h1.52
  text "MATTE" at 322.439,86.734 h1.52
  text "SEMI-GLOSS" at 338.125,86.717 h1.52
  text "IMMERSION GOLD (ENIG)" at 314.819,82.345 h1.52
  text "ENEPIG" at 348.793,82.162 h1.52
  text "SURFACE FINISH:" at 287.87,82.136 h1.52
  text "X" at 310.298,82.136 h1.52
  text "IMM. TIN/SILVER OR EQUIV" at 296.24,78.649 h1.52
  text "OTHER" at 332.599,78.549 h1.52
  text "ARRAY/PANEL:" at 287.87,74.602 h1.52
  text "CUT AND TRIM PER M1 BOARD OUTLINE" at 314.819,74.393 h1.52
  text "N.C. ROUTE" at 314.819,70.94 h1.52
  text "X" at 332.295,70.94 h1.52
  text "V. SCORE" at 336.816,70.94 h1.52
  text "CERTIFICATION:" at 287.87,67.66 h1.52
  text "MATERIALS AND WORKMANSHIP FOR ALL PCBS" at 306.285,67.66 h1.52
  text "TO MEET OR EXCEED THE REQUIREMENTS OF:" at 306.285,65.271 h1.52
  text "X" at 297.078,62.003 h1.52
  text "ANSI IPC-A-600F CLASS ->" at 300.329,62.003 h1.52
  text "X" at 342.188,62.003 h1.52
  text "2" at 344.982,62.003 h1.52
  text "1" at 336.981,61.965 h1.52
  text "3" at 353.973,61.965 h1.52
  text "X" at 317.702,58.252 h1.52
  text "RoHS" at 320.953,58.252 h1.52
  text "OTHER" at 337.321,58.252 h1.52
  text "PER ORDER" at 347.407,58.252 h1.52
  text "ALL BOARDS MUST MEET OR EXCEED UL94-V0 REQUIREMENTS." at 288.569,54.345 h1.52
  text "PCB MUST BEAR THE UL94V-0 UL REGISTERED MATERIAL ID NUMBER" at 288.569,51.397 h1.52
  text "ADDITIONAL REQUIREMENTS:" at 287.87,47.094 h1.52
  text "MICROSECTION:" at 289.769,44.373 h1.52
  text "YES" at 312.775,44.373 h1.52
  text "REQUIRED" at 334.657,40.707 h1.52
  text "BARE BOARD ELEC. TEST:" at 289.769,40.634 h1.52
  text "NONE" at 322.935,40.634 h1.52
  text "X" at 331.66,40.634 h1.52
  text "PER ORDER" at 349.693,40.634 h1.52
  text "XX MIL VIAS REQUIRE NON-CONDUCTIVE FILL AND PLANARIZE" at 294.04,35.428 h1.5
  text "XX MIL VIAS REQUIRE CONDUCTIVE FILL AND PLANARIZE" at 294.243,32.787 h1.52
  text "OUTER XX MIL TRACES REQUIRE 50 OHM SINGLE-ENDED IMPEDANCE" at 294.218,28.637 h1.47
  text "LAYER 2 & 3 (INNER LAYERS) XX MIL WIDE, XX MIL SPACE / TRACES REQUIRE 100 OHM DIFFERENTIAL IMPEDANCE" at 294.015,22.65 h1.52
  text ".Layer_Name" at 14.656,-21.806 h1.52
M11 Gerber Information:
  lines w0.254: -7.417,-23.626 160.223,-23.626 ; -7.417,-18.462 160.274,-18.462 ; -7.417,-13.297 -7.417,-28.791 94.31,-28.791 160.274,-28.791 160.274,-13.297 -7.404,-13.297 -7.404,-28.791 32.614,-28.791 ; 55.194,-28.791 55.194,-13.297 ; 87.376,-18.462 87.376,-13.297 ; 108.712,-18.462 108.712,-13.297 ; 124.511,-28.956 124.511,-23.804
  text "ALL ARTWORK VIEWED FROM TOP SIDE" at -5.804,-16.654 h1.52
  text "BOARD #:" at 57.099,-16.654 h1.52
  text ".PRJ_Number" at 70.955,-16.654 h1.52
  text "REV:" at 92.405,-16.654 h1.52
  text ".PCB_Rev" at 99.809,-16.654 h1.52
  text "SVN REV:" at 113.69,-16.654 h1.52
  text ".VersionControl_RevNumber" at 126.543,-16.654 h1.52
  text "LAYER NAME =" at -5.804,-21.806 h1.52
  text "TID #:" at 57.099,-21.819 h1.52
  text ".TID" at 70.955,-21.819 h1.52
  text "PLOT NAME =" at -5.804,-27.034 h1.52
  text ".plot_File_Name" at 14.656,-27.034 h1.52
  text "GENERATED    :" at 57.15,-27.034 h1.52
  text ".Print_Date" at 79.235,-27.034 h1.52
  text ".Print_Time" at 97.752,-27.034 h1.52
  text "TEXAS INSTRUMENTS" at 129.87,-27.034 h1.52
M12 Stackup:
  drawing of 191 lines, arcs and shapes, not listed
  text "Layer" at 249.119,194.31 h1.52
  text "Name" at 259.531,194.31 h1.52
  text "Material" at 283.147,194.31 h1.52
  text "Thickness" at 304.985,194.31 h1.52
  text "Constant" at 321.49,194.31 h1.52
  text "Board Layer Stack" at 335.965,194.31 h1.52
  text "Top Overlay" at 259.531,191.262 h1.52
  text "Top Solder" at 259.531,188.214 h1.52
  text "Solder Resist" at 283.147,188.214 h1.52
  text "0.40mil" at 304.985,188.214 h1.52
  text "3.5" at 321.49,188.214 h1.52
  text "1" at 249.119,185.166 h1.52
  text "Top Layer" at 259.531,185.166 h1.52
  text "1.40mil" at 304.985,185.166 h1.52
  text "Dielectric1" at 259.531,182.118 h1.52
  text "FR-4" at 283.147,182.118 h1.52
  text "59.20mil" at 304.985,182.118 h1.52
  text "4.8" at 321.49,182.118 h1.52
  text "2" at 249.119,179.07 h1.52
  text "Bottom Layer" at 259.531,179.07 h1.52
  text "1.40mil" at 304.985,179.07 h1.52
  text "Bottom Solder" at 259.531,176.022 h1.52
  text "Solder Resist" at 283.147,176.022 h1.52
  text "0.40mil" at 304.985,176.022 h1.52
  text "3.5" at 321.49,176.022 h1.52
  text "Bottom Overlay" at 259.531,172.974 h1.52
  text ".Layer_Name" at 14.656,-21.806 h1.52
M13 Component Bodies Top:
  text ".Layer_Name" at 14.656,-21.806 h1.52
M14 Component Bodies Bottom:
  text ".Layer_Name" at 14.656,-21.806 h1.52
M15 Courtyards Top:
  text ".Layer_Name" at 14.656,-21.806 h1.52
M16 Courtyards Bottom:
  text ".Layer_Name" at 14.656,-21.806 h1.52
Drill Drawing:
  circle w0.254: c136.241,77.851 r0.703
  lines w0.254: 135.538,73.986 136.944,73.986 136.944,75.392 135.538,75.392 135.538,73.986 ; 135.538,80.662 135.89,80.662 136.241,80.311 136.593,80.662 136.944,80.662 136.593,81.014 136.944,81.365 136.593,81.365 136.241,81.716 135.89,81.365 135.538,81.365 135.89,81.014 135.538,80.662 ; 135.538,83.473 136.241,83.825 136.944,83.473 136.593,84.176 136.944,84.879 136.241,84.527 135.538,84.879 135.89,84.176 135.538,83.473
  lines w0.305: 134.264,73.038 216.362,73.038 ; 134.264,85.687 216.362,85.687 ; 142.85,69.875 142.85,88.849 ; 151.287,69.875 151.287,88.849 ; 167.453,69.875 167.453,88.849 ; 174.037,69.875 174.037,88.849 ; 183.568,69.875 183.568,88.849 ; 201.972,69.875 201.972,88.849 ; 134.264,69.875 216.362,69.875 216.362,88.849 134.264,88.849 134.264,69.875
  text "Symbol" at 136.162,86.636 h1.83
  text "Quantity" at 143.799,86.636 h1.83
  text "Finished Hole Size" at 152.235,86.636 h1.83
  text "Plated" at 168.402,86.636 h1.83
  text "Hole Type" at 174.986,86.636 h1.83
  text "Drill Layer Pair" at 184.517,86.636 h1.83
  text "Hole Tolerance" at 202.92,86.636 h1.83
  text "9" at 143.799,83.473 h1.52
  text "11.81mil (0.300mm)" at 152.235,83.473 h1.52
  text "PTH" at 168.402,83.473 h1.52
  text "Round" at 174.986,83.473 h1.52
  text "Top Layer - Bottom Layer" at 184.517,83.473 h1.52
  text "30" at 143.799,80.311 h1.52
  text "19.69mil (0.500mm)" at 152.235,80.311 h1.52
  text "PTH" at 168.402,80.311 h1.52
  text "Round" at 174.986,80.311 h1.52
  text "Top Layer - Bottom Layer" at 184.517,80.311 h1.52
  text "4" at 143.799,77.149 h1.52
  text "50.00mil (1.270mm)" at 152.235,77.149 h1.52
  text "PTH" at 168.402,77.149 h1.52
  text "Round" at 174.986,77.149 h1.52
  text "Top Layer - Bottom Layer" at 184.517,77.149 h1.52
  text "7" at 143.799,73.986 h1.52
  text "63.00mil (1.600mm)" at 152.235,73.986 h1.52
  text "PTH" at 168.402,73.986 h1.52
  text "Round" at 174.986,73.986 h1.52
  text "Top Layer - Bottom Layer" at 184.517,73.986 h1.52
  text "50 Total" at 143.799,70.824 h1.52
  text ".Layer_Name" at 14.656,-21.806 h1.52
M17 Embedded Cavity:
  text ".Layer_Name" at 14.656,-21.806 h1.52
M18 Embedded Assembly:
  text ".Layer_Name" at 14.656,-21.806 h1.52
M19 Embedded Keepout:
  text ".Layer_Name" at 14.656,-21.806 h1.52

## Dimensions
64.89,8.535 to 64.89,29.972 on Top Overlay
25.654,8.535 to 64.89,8.535 on Top Overlay
0,-10.16 to 25.4,-10.16 on M2 Board Dimensions
0,0 to 0,39.37 on M2 Board Dimensions
0,0 to 68.58,0 on M2 Board Dimensions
